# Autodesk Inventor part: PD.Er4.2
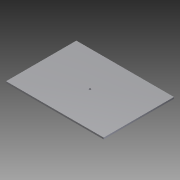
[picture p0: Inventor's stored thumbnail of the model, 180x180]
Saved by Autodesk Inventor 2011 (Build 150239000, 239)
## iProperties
Created: 2014-06
Part Number: PD.Er4.2
Document SubType Name: Modeling
Designer: Evgeny
Density: 1 g/cm^3
Author: Evgeny
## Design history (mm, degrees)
sketch "Эскиз1"
  geometry: L1 (-46.5, 33.5)-(46.5, 33.5); L2 (46.5, 33.5)-(46.5, -33.5); L3 (46.5, -33.5)-(-46.5, -33.5); L4 (-46.5, -33.5)-(-46.5, 33.5); C1 r 0.85 at (0, 0); 1 further point
  constraints: 8 end point, 2 parallel, 1 centre point, 1 coincident, 1 horizontal, 1 perpendicular
  dimensions: "d0" = 93 distance between parallel lines of L2 L4; "d1" = 67 distance between parallel lines of L3 L1; "d2" = 46.5 distance from line of L4 point (0, 0); "d3" = 33.5 distance from line of L3 point (0, 0); "d4" = 1.7 diameter of C1
extrude "Выдавливание1" new body sketch "Эскиз1" distance "d5" = 1.5; taper "d6" = 0 deg
node "Твердое тело1"
